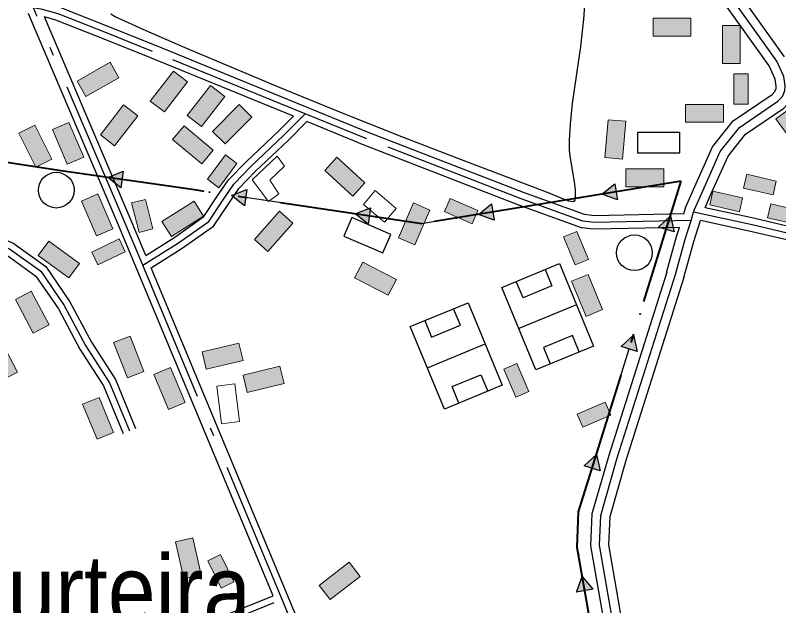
# Model space of a CAD drawing. Extents: x -64005 to -55000, y -89025 to -80000.
# Drawn here: x -62966 to -62111, y -82170 to -81509 of the extents above; entities that cross this region are included whole.
import ezdxf
from ezdxf.enums import TextEntityAlignment as Align

# ---------------------------------------------------------------- set-up
doc = ezdxf.new("R2010")
doc.units = 0
doc.header["$LTSCALE"] = 32
doc.linetypes.add('DOT_DASHED', pattern=[7.7, 5, -1.2, 0.3, -1.2])
doc.linetypes.add('LONG_DASHED', pattern=[7.5, 6, -1.5])
for name, color, linetype, lineweight in [('10', 7, 'Continuous', 25), ('14', 7, 'Continuous', 25), ('16', 7, 'Continuous', 25), ('18', 7, 'Continuous', 25), ('21', 7, 'Continuous', 25), ('24', 7, 'Continuous', 25), ('39', 7, 'LONG_DASHED', 25), ('6', 7, 'Continuous', 25), ('7', 7, 'Continuous', 13)]:
    doc.layers.add(name, color=color, linetype=linetype, lineweight=lineweight)
doc.layers.add('45', color=7, linetype='Continuous')

msp = doc.modelspace()

# ---------------------------------------------------------------- hatches: boundary and pattern name
at = {"layer": '18'}
for points in [[(-62847.82, -81702.16), (-62862.36, -81690.72), (-62845.19, -81683.84)], [(-62291.56, -81715.93), (-62308.86, -81709.4), (-62294.55, -81697.68)], [(-62709.33, -81722.33), (-62723.82, -81710.82), (-62706.61, -81704.03)], [(-62429.7, -81738.62), (-62447.01, -81732.09), (-62432.7, -81720.37)], [(-62570.85, -81742.91), (-62585.34, -81731.41), (-62568.13, -81724.62)], [(-62245.7, -81746.25), (-62232.11, -81733.69), (-62228.03, -81751.73)], [(-62287.2, -81879.96), (-62273.62, -81867.4), (-62269.53, -81885.44)], [(-62328.7, -82013.66), (-62315.12, -82001.11), (-62311.03, -82019.15)], [(-62337.26, -82154.94), (-62330.91, -82137.57), (-62319.03, -82151.75)]]:
    msp.add_hatch(color=256, dxfattribs=at).paths.add_polyline_path(points)
at = {"layer": '7'}
for points in [[(-62209.14, -81512.45), (-62251.64, -81512.45), (-62251.64, -81532.45), (-62209.14, -81532.45)], [(-62154, -81563.21), (-62154, -81520.71), (-62174, -81520.71), (-62174, -81563.21)], [(-62859.76, -81561.7), (-62896.66, -81582.79), (-62886.74, -81600.16), (-62849.84, -81579.07)], [(-62788.67, -81571.55), (-62814.73, -81605.12), (-62798.93, -81617.39), (-62772.87, -81583.82)], [(-62145.05, -81608.65), (-62145.05, -81574.65), (-62161.05, -81574.65), (-62161.05, -81608.65)], [(-62747.15, -81587.67), (-62773.21, -81621.24), (-62757.41, -81633.51), (-62731.35, -81599.94)], [(-62844.54, -81609.51), (-62870.6, -81643.08), (-62854.8, -81655.35), (-62828.74, -81621.78)], [(-62715.09, -81609), (-62745.12, -81639.07), (-62730.97, -81653.2), (-62700.94, -81623.13)], [(-62172.82, -81608.96), (-62215.32, -81608.96), (-62215.32, -81628.96), (-62172.82, -81628.96)], [(-62113.94, -81624.99), (-62088.96, -81659.37), (-62072.78, -81647.61), (-62097.76, -81613.23)], [(-62924.37, -81636.88), (-62907.69, -81675.97), (-62889.29, -81668.12), (-62905.97, -81629.03)], [(-62285.77, -81670.18), (-62281.93, -81627.85), (-62301.85, -81626.04), (-62305.69, -81668.37)], [(-62961.89, -81641.19), (-62942.9, -81679.21), (-62925.01, -81670.27), (-62944, -81632.25)], [(-62744.24, -81660.19), (-62776.76, -81632.83), (-62789.64, -81648.13), (-62757.12, -81675.49)], [(-62730.49, -81665.4), (-62750.7, -81692.74), (-62737.83, -81702.26), (-62717.62, -81674.92)], [(-62619.11, -81682.88), (-62587.77, -81711.59), (-62574.27, -81696.84), (-62605.61, -81668.13)], [(-62282.07, -81701.21), (-62239.57, -81701.21), (-62239.57, -81681.21), (-62282.07, -81681.21)], [(-62113.59, -81694.74), (-62146.73, -81687.13), (-62150.31, -81702.72), (-62117.17, -81710.33)], [(-62151.4, -81713.52), (-62184.54, -81705.91), (-62188.12, -81721.5), (-62154.98, -81729.11)], [(-62891.91, -81717.18), (-62874.99, -81756.16), (-62856.65, -81748.2), (-62873.57, -81709.22)], [(-62447.77, -81727.85), (-62478.9, -81714.18), (-62485.33, -81728.83), (-62454.2, -81742.5)], [(-62811.71, -81748.31), (-62820.1, -81715.36), (-62835.61, -81719.31), (-62827.22, -81752.26)], [(-62765.72, -81717.17), (-62801.63, -81739.89), (-62790.94, -81756.79), (-62755.03, -81734.07)], [(-62519.86, -81719.3), (-62536.67, -81758.33), (-62518.3, -81766.24), (-62501.49, -81727.21)], [(-62086.67, -81727.93), (-62119.81, -81720.32), (-62123.39, -81735.91), (-62090.25, -81743.52)], [(-62669.97, -81728.49), (-62698.09, -81760.36), (-62683.09, -81773.59), (-62654.97, -81741.72)], [(-62323.99, -81782.58), (-62336.98, -81751.16), (-62351.77, -81757.28), (-62338.78, -81788.7)], [(-62894.05, -81787.15), (-62928.33, -81762.03), (-62940.15, -81778.17), (-62905.87, -81803.29)], [(-62849.72, -81759.51), (-62880.33, -81774.32), (-62873.36, -81788.73), (-62842.75, -81773.92)], [(-62585.87, -81803.16), (-62548.13, -81822.7), (-62538.93, -81804.94), (-62576.67, -81785.4)], [(-62308.13, -81838.64), (-62324.37, -81799.36), (-62342.85, -81807), (-62326.61, -81846.28)], [(-62965.61, -81827.42), (-62945.76, -81865), (-62928.07, -81855.66), (-62947.92, -81818.08)], [(-62856.01, -81875.67), (-62840.37, -81915.19), (-62821.77, -81907.83), (-62837.41, -81868.31)], [(-63001.06, -81880.64), (-62981.23, -81918.23), (-62963.54, -81908.9), (-62983.37, -81871.31)], [(-62715.41, -81876.09), (-62756.72, -81886.05), (-62752.03, -81905.49), (-62710.72, -81895.53)], [(-62669.57, -81901.87), (-62710.83, -81912.04), (-62706.05, -81931.46), (-62664.78, -81921.29)], [(-62390.57, -81930.26), (-62404.06, -81899.05), (-62418.75, -81905.4), (-62405.26, -81936.61)], [(-62810.57, -81911.31), (-62794.21, -81950.53), (-62775.75, -81942.83), (-62792.11, -81903.61)], [(-62890.54, -81944.67), (-62874.28, -81983.94), (-62855.8, -81976.29), (-62872.06, -81937.02)], [(-62330.25, -81970.5), (-62299.04, -81957.01), (-62305.39, -81942.32), (-62336.6, -81955.81)], [(-62786.51, -82098.62), (-62777.29, -82140.1), (-62757.77, -82135.76), (-62766.99, -82094.28)], [(-62720.94, -82143.39), (-62735.91, -82112.86), (-62750.28, -82119.91), (-62735.31, -82150.44)], [(-62592.04, -82121.65), (-62625.66, -82147.65), (-62613.42, -82163.47), (-62579.8, -82137.47)]]:
    msp.add_hatch(color=256, dxfattribs=at).paths.add_polyline_path(points)

# ---------------------------------------------------------------- linework, layer by layer
at = {"layer": '10'}
for centre in [(-62919.96, -81704.94), (-62272.49, -81775.07)]:
    msp.add_circle(centre, 20, dxfattribs=at)
at = {"layer": '14'}
for p, q in [((-62337.29, -81833.25), (-62401.97, -81859.99)), ((-62504.36, -81903.9), (-62439.68, -81877.16))]:
    msp.add_line(p, q, dxfattribs=at)
for points in [[(-62356.39, -81787.04), (-62318.18, -81879.45), (-62382.87, -81906.2), (-62421.08, -81813.79)], [(-62485.26, -81950.11), (-62523.47, -81857.7), (-62458.78, -81830.95), (-62420.57, -81923.36)]]:
    msp.add_lwpolyline(points, close=True, dxfattribs=at)
for points in [[(-62372.56, -81793.73), (-62364.92, -81812.21), (-62397.27, -81825.58), (-62404.91, -81807.1)], [(-62507.3, -81851.01), (-62499.66, -81869.49), (-62467.31, -81856.12), (-62474.95, -81837.64)], [(-62334.35, -81886.14), (-62341.99, -81867.66), (-62374.34, -81881.03), (-62366.7, -81899.51)], [(-62469.09, -81943.42), (-62476.73, -81924.94), (-62444.38, -81911.57), (-62436.74, -81930.05)]]:
    msp.add_lwpolyline(points, dxfattribs=at)
at = {"layer": '16'}
for points in [[(-62269.06, -81640.48), (-62269.06, -81662.98), (-62221.56, -81662.98), (-62221.56, -81640.48)], [(-62589.1, -81735.66), (-62598, -81756.33), (-62554.38, -81775.12), (-62545.48, -81754.45)]]:
    msp.add_lwpolyline(points, close=True, dxfattribs=at)
at = {"layer": '18'}
for p, q in [((-62773.28, -81703.52), (-62846.51, -81693)), ((-62220.05, -81694.83), (-62293.05, -81706.81)), ((-62634.79, -81724.06), (-62707.97, -81713.18)), ((-62358.2, -81717.5), (-62431.2, -81729.49)), ((-62258.79, -81819.65), (-62236.86, -81748.99)), ((-62300.3, -81953.35), (-62278.37, -81882.7)), ((-62315.37, -82226.22), (-62328.14, -82153.35))]:
    msp.add_line(p, q, dxfattribs=at)
at = {"layer": '18', "linetype": 'DOT_DASHED', "lineweight": 40}
for points in [[(-62220.05, -81694.83), (-62338.5, -81714.26), (-62510.53, -81742.53), (-62762.72, -81705.04), (-62917.22, -81682.84), (-63082.62, -81657.94), (-63182.49, -81662.88), (-63319.9, -81696.94)], [(-62343.25, -82631.81), (-62318.39, -82564.8), (-62277.61, -82443.92), (-62314.58, -82230.74), (-62336.62, -82104.99), (-62334.94, -82064.96), (-62220.05, -81694.83)]]:
    msp.add_lwpolyline(points, dxfattribs=at)
at = {"layer": '18'}
for points in [[(-62911.86, -81683.61), (-62917.22, -81682.84), (-62985.02, -81672.63)], [(-62496.35, -81740.2), (-62510.53, -81742.53), (-62569.49, -81733.76)], [(-62335.91, -82088.08), (-62334.94, -82064.96), (-62319.87, -82016.41)]]:
    msp.add_lwpolyline(points, dxfattribs=at)
for points in [[(-62847.82, -81702.16), (-62862.36, -81690.72), (-62845.19, -81683.84)], [(-62291.56, -81715.93), (-62308.86, -81709.4), (-62294.55, -81697.68)], [(-62709.33, -81722.33), (-62723.82, -81710.82), (-62706.61, -81704.03)], [(-62429.7, -81738.62), (-62447.01, -81732.09), (-62432.7, -81720.37)], [(-62570.85, -81742.91), (-62585.34, -81731.41), (-62568.13, -81724.62)], [(-62245.7, -81746.25), (-62232.11, -81733.69), (-62228.03, -81751.73)], [(-62287.2, -81879.96), (-62273.62, -81867.4), (-62269.53, -81885.44)], [(-62328.7, -82013.66), (-62315.12, -82001.11), (-62311.03, -82019.15)], [(-62337.26, -82154.94), (-62330.91, -82137.57), (-62319.03, -82151.75)]]:
    msp.add_lwpolyline(points, close=True, dxfattribs=at)
for centre in [(-62887.11, -81687.17), (-62748.54, -81707.15), (-62333.53, -81713.45), (-62224.7, -81709.82), (-62610.06, -81727.73), (-62471.68, -81736.15), (-62266.21, -81843.52), (-62307.71, -81977.23), (-62335.23, -82112.95)]:
    msp.add_circle(centre, 0.5, dxfattribs=at)
at = {"layer": '21'}
msp.add_line((-62660.19, -82160.35), (-62813.86, -81792.03), dxfattribs=at)
for points in [[(-62217.29, -81731.46), (-62317.68, -81733.73), (-62328.34, -81732.3), (-62396.56, -81707.73), (-62569.5, -81640.57), (-62809.55, -81542.61), (-62860.95, -81521.99), (-62915.5, -81500.56), (-62933.62, -81495.2), (-62940.2, -81493.99)], [(-62676.96, -82159.11), (-62852.01, -81739.55), (-62948.78, -81512.64), (-62950.98, -81507.25)], [(-62819.72, -81777.99), (-62838.19, -81733.71), (-62933.19, -81510.97)], [(-62654.46, -81622.1), (-62815.17, -81556.51), (-62866.49, -81535.93), (-62920.38, -81514.76), (-62933.19, -81510.97)], [(-62819.72, -81777.99), (-62787.2, -81757.5), (-62754.76, -81734.53), (-62739.99, -81712.54), (-62727.1, -81693.38), (-62707.2, -81673.07), (-62670.8, -81638.54), (-62654.46, -81622.1)], [(-62813.86, -81792.03), (-62778.86, -81769.98), (-62743.84, -81745.17), (-62727.55, -81720.9), (-62715.42, -81702.9), (-62696.68, -81683.77), (-62660.32, -81649.28), (-62639.41, -81628.24)], [(-62222.01, -81746.57), (-62318.5, -81748.75), (-62331.92, -81746.96), (-62401.82, -81721.77), (-62575.04, -81654.51), (-62639.41, -81628.24)], [(-61965.47, -81790.27), (-61986.6, -81781.71), (-62025.67, -81765.75), (-62054.25, -81756.45), (-62092.02, -81747.6), (-62139.01, -81736.45), (-62193.42, -81724.59)], [(-61946.93, -81813.96), (-61992.26, -81795.61), (-62030.83, -81779.85), (-62058.29, -81770.91), (-62095.46, -81762.2), (-62142.33, -81751.07), (-62198.64, -81738.8)], [(-63007.5, -81743.27), (-62998.54, -81752.23), (-62968.58, -81764.01), (-62931.86, -81790.42), (-62904.69, -81830.04), (-62880.67, -81875.25), (-62853.76, -81917.03), (-62831.14, -81971.66)], [(-63012.97, -81759.01), (-63006.94, -81765.05), (-62975.82, -81777.29), (-62942.74, -81801.06), (-62917.55, -81837.82), (-62893.63, -81882.85), (-62867.1, -81924.01), (-62845, -81977.4)], [(-63070.17, -82319.73), (-63056.38, -82311.54), (-62676.96, -82159.11)], [(-62576.49, -82363.4), (-62617.12, -82263.58), (-62660.19, -82160.35)]]:
    msp.add_lwpolyline(points, dxfattribs=at)
at = {"layer": '24'}
msp.add_lwpolyline([(-62328.24, -81498.08), (-62329.42, -81513.41), (-62332.83, -81543.92), (-62342.11, -81608.03), (-62344.38, -81630.96), (-62345.59, -81649.31), (-62345.43, -81660.39), (-62344.41, -81669.25), (-62339.85, -81695.78), (-62338.86, -81704.63), (-62338.71, -81714.02), (-62339.2, -81716.32), (-62339.85, -81717.38), (-62341.14, -81717.87), (-62346.06, -81717.12), (-62350.01, -81715.9), (-62367.8, -81708.12), (-62469.11, -81669.91), (-62533.16, -81645.21), (-62600.7, -81618.25), (-62671.74, -81589.07), (-62775.71, -81545.53), (-62819.26, -81526.62), (-62853.93, -81510.88), (-62859.03, -81507.82)], dxfattribs=at)
at = {"layer": '39', "linetype": 'Continuous'}
msp.add_line((-62209.11, -81738.78), (-62206.2, -81729.48), dxfattribs=at)
at = {"layer": '39', "linetype": 'DOT_DASHED'}
msp.add_line((-62667.11, -82163.24), (-62823.22, -81789.06), dxfattribs=at)
at = {"layer": '39', "linetype": 'Continuous'}
for points in [[(-62113.04, -81560.58), (-62234.82, -81390.04), (-62264.76, -81347.98)], [(-62105.63, -81597.3), (-62103.88, -81593.38), (-62103.53, -81588.14), (-62105.1, -81577.84), (-62113.04, -81560.58)], [(-62154.88, -81634.84), (-62111.73, -81605.43), (-62106.84, -81600.02), (-62105.63, -81597.3)], [(-62197.16, -81708.2), (-62176.28, -81661.6), (-62154.88, -81634.84)], [(-62206.2, -81729.48), (-62205.5, -81727.23), (-62197.16, -81708.2)], [(-62226.6, -81799.43), (-62215.61, -81759.64), (-62209.11, -81738.78)], [(-62278.81, -82286.61), (-62293.27, -82207.77), (-62311.74, -82102.53), (-62310.11, -82069.08), (-62291.64, -82004.81), (-62226.6, -81799.43)]]:
    msp.add_lwpolyline(points, dxfattribs=at)
at = {"layer": '39', "linetype": 'DOT_DASHED'}
for points in [[(-62823.22, -81789.06), (-62845.1, -81736.63), (-62941.86, -81509.75), (-62945.59, -81500.62)], [(-62641.21, -81619.41), (-62812.36, -81549.56), (-62863.72, -81528.96), (-62917.94, -81507.66), (-62935.37, -81502.5), (-62945.59, -81500.62)], [(-62823.22, -81789.06), (-62783.03, -81763.74), (-62749.3, -81739.85), (-62733.77, -81716.72), (-62721.26, -81698.14), (-62701.94, -81678.42), (-62665.56, -81643.91), (-62641.21, -81619.41)], [(-62209.11, -81738.78), (-62318.09, -81741.24), (-62330.13, -81739.63), (-62399.19, -81714.75), (-62572.27, -81647.54), (-62641.21, -81619.41)], [(-61942.36, -81807.72), (-61989.43, -81788.66), (-62028.25, -81772.8), (-62056.27, -81763.68), (-62093.74, -81754.9), (-62140.67, -81743.76), (-62206.2, -81729.48)], [(-63012.8, -81748.57), (-63002.74, -81758.64), (-62972.2, -81770.65), (-62937.3, -81795.74), (-62911.12, -81833.93), (-62887.15, -81879.05), (-62860.43, -81920.52), (-62838.07, -81974.53)], [(-63074.65, -82331.12), (-63053.05, -82318.28), (-62667.11, -82163.24)], [(-62580.58, -82373.23), (-62624.05, -82266.44), (-62667.11, -82163.24)]]:
    msp.add_lwpolyline(points, dxfattribs=at)
at = {"layer": '6'}
for p, q in [((-62193.42, -81724.59), (-62188, -81712.22)), ((-62236.24, -81796.77), (-62236.01, -81795.93))]:
    msp.add_line(p, q, dxfattribs=at)
for points in [[(-62121.74, -81565.61), (-62242.96, -81395.85), (-62504.22, -81028.9)], [(-62104.33, -81555.57), (-62226.67, -81384.23), (-62244.49, -81359.21)], [(-62161.78, -81627.45), (-62118.35, -81597.84), (-62115.32, -81594.49), (-62113.74, -81590.94), (-62113.58, -81588.58), (-62114.77, -81580.74), (-62121.74, -81565.61)], [(-62147.99, -81642.24), (-62105.11, -81613.02), (-62098.36, -81605.54), (-62096.56, -81601.43)], [(-62206.32, -81704.18), (-62184.89, -81656.35), (-62161.78, -81627.45)], [(-62188, -81712.22), (-62167.66, -81666.85), (-62147.99, -81642.24)], [(-62217.29, -81731.46), (-62214.88, -81723.72), (-62206.32, -81704.18)], [(-62217.22, -81802.92), (-62206.02, -81762.46), (-62198.64, -81738.8)], [(-62236.01, -81795.93), (-62225.2, -81756.82), (-62222.01, -81746.57)], [(-62236.24, -81796.77), (-62301.21, -82001.92), (-62320.04, -82067.43), (-62321.78, -82103.17), (-62303.11, -82209.54), (-62291.15, -82274.79), (-62290.12, -82280.39)], [(-62217.22, -81802.92), (-62282.07, -82007.69), (-62300.18, -82070.73), (-62301.7, -82101.9), (-62283.43, -82206), (-62255.33, -82359.23), (-62242.33, -82442.07), (-62242.33, -82463.79), (-62248.14, -82480.76)]]:
    msp.add_lwpolyline(points, dxfattribs=at)
at = {"layer": '7'}
for points in [[(-62209.14, -81512.45), (-62251.64, -81512.45), (-62251.64, -81532.45), (-62209.14, -81532.45)], [(-62154, -81563.21), (-62154, -81520.71), (-62174, -81520.71), (-62174, -81563.21)], [(-62859.76, -81561.7), (-62896.66, -81582.79), (-62886.74, -81600.16), (-62849.84, -81579.07)], [(-62788.67, -81571.55), (-62814.73, -81605.12), (-62798.93, -81617.39), (-62772.87, -81583.82)], [(-62145.05, -81608.65), (-62145.05, -81574.65), (-62161.05, -81574.65), (-62161.05, -81608.65)], [(-62747.15, -81587.67), (-62773.21, -81621.24), (-62757.41, -81633.51), (-62731.35, -81599.94)], [(-62844.54, -81609.51), (-62870.6, -81643.08), (-62854.8, -81655.35), (-62828.74, -81621.78)], [(-62715.09, -81609), (-62745.12, -81639.07), (-62730.97, -81653.2), (-62700.94, -81623.13)], [(-62172.82, -81608.96), (-62215.32, -81608.96), (-62215.32, -81628.96), (-62172.82, -81628.96)], [(-62113.94, -81624.99), (-62088.96, -81659.37), (-62072.78, -81647.61), (-62097.76, -81613.23)], [(-62924.37, -81636.88), (-62907.69, -81675.97), (-62889.29, -81668.12), (-62905.97, -81629.03)], [(-62285.77, -81670.18), (-62281.93, -81627.85), (-62301.85, -81626.04), (-62305.69, -81668.37)], [(-62961.89, -81641.19), (-62942.9, -81679.21), (-62925.01, -81670.27), (-62944, -81632.25)], [(-62744.24, -81660.19), (-62776.76, -81632.83), (-62789.64, -81648.13), (-62757.12, -81675.49)], [(-62730.49, -81665.4), (-62750.7, -81692.74), (-62737.83, -81702.26), (-62717.62, -81674.92)], [(-62664.23, -81677.96), (-62672.76, -81666.97), (-62700.61, -81693.22), (-62682.31, -81717.71), (-62670.58, -81709), (-62680.9, -81693.89)], [(-62619.11, -81682.88), (-62587.77, -81711.59), (-62574.27, -81696.84), (-62605.61, -81668.13)], [(-62282.07, -81701.21), (-62239.57, -81701.21), (-62239.57, -81681.21), (-62282.07, -81681.21)], [(-62113.59, -81694.74), (-62146.73, -81687.13), (-62150.31, -81702.72), (-62117.17, -81710.33)], [(-62563, -81705.47), (-62539.43, -81725.33), (-62552.24, -81740.68), (-62575.81, -81720.83)], [(-62151.4, -81713.52), (-62184.54, -81705.91), (-62188.12, -81721.5), (-62154.98, -81729.11)], [(-62891.91, -81717.18), (-62874.99, -81756.16), (-62856.65, -81748.2), (-62873.57, -81709.22)], [(-62447.77, -81727.85), (-62478.9, -81714.18), (-62485.33, -81728.83), (-62454.2, -81742.5)], [(-62811.71, -81748.31), (-62820.1, -81715.36), (-62835.61, -81719.31), (-62827.22, -81752.26)], [(-62765.72, -81717.17), (-62801.63, -81739.89), (-62790.94, -81756.79), (-62755.03, -81734.07)], [(-62519.86, -81719.3), (-62536.67, -81758.33), (-62518.3, -81766.24), (-62501.49, -81727.21)], [(-62086.67, -81727.93), (-62119.81, -81720.32), (-62123.39, -81735.91), (-62090.25, -81743.52)], [(-62669.97, -81728.49), (-62698.09, -81760.36), (-62683.09, -81773.59), (-62654.97, -81741.72)], [(-62323.99, -81782.58), (-62336.98, -81751.16), (-62351.77, -81757.28), (-62338.78, -81788.7)], [(-62894.05, -81787.15), (-62928.33, -81762.03), (-62940.15, -81778.17), (-62905.87, -81803.29)], [(-62849.72, -81759.51), (-62880.33, -81774.32), (-62873.36, -81788.73), (-62842.75, -81773.92)], [(-62585.87, -81803.16), (-62548.13, -81822.7), (-62538.93, -81804.94), (-62576.67, -81785.4)], [(-62308.13, -81838.64), (-62324.37, -81799.36), (-62342.85, -81807), (-62326.61, -81846.28)], [(-62965.61, -81827.42), (-62945.76, -81865), (-62928.07, -81855.66), (-62947.92, -81818.08)], [(-62856.01, -81875.67), (-62840.37, -81915.19), (-62821.77, -81907.83), (-62837.41, -81868.31)], [(-63001.06, -81880.64), (-62981.23, -81918.23), (-62963.54, -81908.9), (-62983.37, -81871.31)], [(-62715.41, -81876.09), (-62756.72, -81886.05), (-62752.03, -81905.49), (-62710.72, -81895.53)], [(-62669.57, -81901.87), (-62710.83, -81912.04), (-62706.05, -81931.46), (-62664.78, -81921.29)], [(-62390.57, -81930.26), (-62404.06, -81899.05), (-62418.75, -81905.4), (-62405.26, -81936.61)], [(-62810.57, -81911.31), (-62794.21, -81950.53), (-62775.75, -81942.83), (-62792.11, -81903.61)], [(-62720.14, -81921.94), (-62714.95, -81964.13), (-62734.81, -81966.57), (-62740, -81924.39)], [(-62890.54, -81944.67), (-62874.28, -81983.94), (-62855.8, -81976.29), (-62872.06, -81937.02)], [(-62330.25, -81970.5), (-62299.04, -81957.01), (-62305.39, -81942.32), (-62336.6, -81955.81)], [(-62786.51, -82098.62), (-62777.29, -82140.1), (-62757.77, -82135.76), (-62766.99, -82094.28)], [(-62720.94, -82143.39), (-62735.91, -82112.86), (-62750.28, -82119.91), (-62735.31, -82150.44)], [(-62592.04, -82121.65), (-62625.66, -82147.65), (-62613.42, -82163.47), (-62579.8, -82137.47)]]:
    msp.add_lwpolyline(points, close=True, dxfattribs=at)

# ---------------------------------------------------------------- texts
at = {"layer": '45', "width": 0.9}
msp.add_text('Murteira', height=80, rotation=0.007, dxfattribs=at).set_placement((-62878.22, -82193.55), align=Align.CENTER)

doc.saveas('drawing.dxf')
